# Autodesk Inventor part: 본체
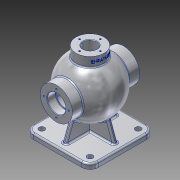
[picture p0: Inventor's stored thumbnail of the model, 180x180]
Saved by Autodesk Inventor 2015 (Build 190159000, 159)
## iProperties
Created: 2025-08
Part Number: 본체
Material: 알루미늄 6061
Document SubType Name: Modeling
Designer: USER
Density: 2.7 g/cm^3
Appearance: 알루미늄 - 평지
Mass: 1526.21 g
Surface Area: 1175.8 cm^2
Volume: 565.262 cm^3
Author: USER
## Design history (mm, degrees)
sketch "스케치1"
  geometry: L1 (-62.5, 62.5)-(62.5, 62.5); L2 (62.5, 62.5)-(62.5, -62.5); L3 (62.5, -62.5)-(-62.5, -62.5); L4 (-62.5, -62.5)-(-62.5, 62.5); L5 (-62.5, 62.5)-(62.5, -62.5); L6 (62.5, 62.5)-(-62.5, -62.5); 1 further point
  constraints: 12 end point, 2 midpoint, 2 parallel, 1 horizontal, 1 perpendicular
  dimensions: "d0" = 125 distance of L2.end L3.end; "d1" = 125 distance of L1.end L2.end
extrude "돌출1" new body sketch "스케치1" distance "d2" = 10; taper "d3" = 0 deg
sketch "스케치2"
  geometry: L1 (0, 139)-(0, 130); L2 (0, 130)-(0, 31); L3 (62.5, 10)-(62.5, 0) reference; L4 (62.5, 0)-(-62.5, 0) reference; L5 (-62.5, 0)-(-62.5, 10) reference; L6 (-62.5, 10)-(62.5, 10) reference; A1 r 54 centre (0, 85) between (0, 139) and (0, 31); 2 further points
  constraints: 4 end point, 2 point on circle, 2 point on line, 1 centre point, 1 midpoint, 1 vertical, 1 vertical alignment
  dimensions: "d4" = 108 diameter of A1; "d5" = 85 distance from line of A1.centre L4
revolve "회전1" sketch "스케치2" stored, may be unused: angle "d6" = 90 deg
sketch "스케치3"
  geometry: L1 (62.5, 62.5)-(62.5, -62.5) reference; L2 (62.5, -62.5)-(-62.5, -62.5) reference; L3 (-62.5, -62.5)-(-62.5, 62.5) reference; L4 (-62.5, 62.5)-(62.5, 62.5) reference; L5 (-4, 50.5)-(4, 50.5); L6 (4, 50.5)-(4, -50.5); L7 (4, -50.5)-(-4, -50.5); L8 (-4, -50.5)-(-4, 50.5); L9 (-50.5, 4)-(50.5, 4); L10 (50.5, 4)-(50.5, -4); L11 (50.5, -4)-(-50.5, -4); L12 (-50.5, -4)-(-50.5, 4); 1 further point
  constraints: 16 end point, 4 parallel, 2 horizontal, 2 perpendicular
  dimensions: "d7" = 8 distance of L5.end L5.start; "d8" = 12 distance between parallel lines of L5 L4; "d9" = 12 distance between parallel lines of L2 L7; "d10" = 4 distance from line of L8 point (0, 0); "d11" = 8 distance of L11.end L9.start; "d12" = 12 distance between parallel lines of L12 L3; "d13" = 12 distance between parallel lines of L1 L10; "d14" = 4 distance from line of point (0, 0) L9
extrude "돌출2" join sketch "스케치3" stored distance "d15" = 10; taper "d16" = 0 deg
feature "면 기울기1" dims angle "d17" = 20 deg
feature "면 기울기2" dims angle "d18" = 20 deg
feature "면 기울기3" dims angle "d19" = 20 deg
feature "면 기울기4" dims angle "d20" = 20 deg
node "작업 평면1"
sketch "스케치4"
  geometry: C1 r 27 at (0, 0); 1 further point
  constraints: 1 centre point, 1 coincident
  dimensions: "d22" = 54 diameter of C1
extrude "돌출3" join sketch "스케치4" stored distance "d23" = 10; taper "d24" = 0 deg
node "작업 평면2"
sketch "스케치5"
  geometry: C1 r 31 at (0, 85); 1 further point
  constraints: 1 centre point, 1 vertical alignment
  dimensions: "d26" = 62 diameter of C1; "d27" = 85 distance of C1.centre point (0, 0)
extrude "돌출4" join sketch "스케치5" distance "d28" = 130; taper "d29" = 0 deg
sketch "스케치6"
  geometry: L1 (62.5, 0)-(-62.5, 0) reference; L2 (-62.5, 0)-(-62.5, 10) reference; L3 (-62.5, 10)-(-50.5, 10) reference; L4 (-50.5, 10)-(-37.385, 46.034) reference; L5 (-27, 131.765)-(-27, 150) reference; L6 (-27, 150)-(27, 150) reference; L7 (27, 150)-(27, 131.765) reference; L8 (37.385, 46.034)-(50.5, 10) reference; L9 (50.5, 10)-(62.5, 10) reference; L10 (62.5, 10)-(62.5, 0) reference; L11 (0, 129)-(0, 41); A1 r 54 centre (0, 85) between (-27, 131.765) and (-37.385, 46.034) reference; A2 r 54 centre (0, 85) between (37.385, 46.034) and (27, 131.765) reference; A3 r 44 centre (0, 85) between (0, 129) and (0, 41); 1 further point
  constraints: 2 end point, 2 point on circle, 1 centre point, 1 coincident, 1 vertical
  dimensions: "d30" = 88 diameter of A3
revolve "회전2" sketch "스케치6" stored, may be unused: angle "d31" = 360 deg
sketch "스케치7"
  geometry: 1 further point
fillet "모깎기1" dims "d33" = 16
fillet "모깎기2" dims "d34" = 16
sketch "스케치9"
  geometry: 1 further point
hole "구멍1" diameter "d37" = 11; stored, may be unused: countersink angle "d41" = 90 deg, drill point angle "d43" = 0 deg; dims "d38" = 6, "d39" = 4, "d40" = 2, "d42" = 8, "d116" = 10, "d117" = 10
hole "구멍2" diameter "d51" = 30; stored, may be unused: countersink angle "d55" = 90 deg, drill point angle "d57" = 0 deg; dims "d49" = 10, "d50" = 10, "d52" = 6, "d53" = 4, "d54" = 2, "d56" = 8
sketch "스케치11"
  geometry: L1 (0, 0)-(0, 24); 1 further point
  constraints: 2 end point, 1 vertical
  dimensions: "d58" = 24 distance of L1.start L1.end
hole "구멍3" sketch "스케치11" at (0, 24) diameter "d59" = 3.242; stored, may be unused: countersink angle "d63" = 90 deg, drill point angle "d65" = 118 deg; dims "d60" = 12, "d61" = 4, "d62" = 2, "d64" = 15
hole "구멍4" diameter "d68" = 26; stored, may be unused: countersink angle "d72" = 90 deg, drill point angle "d74" = 0 deg; dims "d66" = 10, "d67" = 10, "d69" = 8, "d70" = 4, "d71" = 2, "d73" = 100
sketch "스케치12"
  geometry: 1 further point
sketch "스케치14"
  geometry: C1 r 17.5 at (0, 0); 1 further point
  constraints: 1 centre point
  dimensions: "d78" = 35 diameter of C1
extrude "돌출5" cut sketch "스케치14" distance "d79" = 16; taper "d80" = 0 deg
sketch "스케치15"
  geometry: C1 r 17.5 at (0, 0); 1 further point
  constraints: 1 centre point
  dimensions: "d81" = 35 diameter of C1
extrude "돌출6" cut sketch "스케치15" distance "d82" = 16; taper "d83" = 0 deg
sketch "스케치16"
  geometry: L1 (0, 0)-(0, 20)
  constraints: 2 end point, 1 vertical
  dimensions: "d84" = 20 distance of L1.start L1.end
hole "구멍5" sketch "스케치16" at (0, 20) diameter "d85" = 3.242; stored, may be unused: countersink angle "d89" = 90 deg, drill point angle "d91" = 118 deg; dims "d86" = 9, "d87" = 4, "d88" = 2, "d90" = 11
fillet "모깎기3" dims "d95" = 3
fillet "모깎기4" dims "d96" = 3
fillet "모깎기5" dims "d97" = 3
fillet "모깎기6" dims "d98" = 3
fillet "모깎기7" dims "d99" = 3
sketch "스케치17"
  geometry: L1 (-13, 150)-(13, 150) reference; 2 further points
  constraints: 1 vertical alignment, 1 other
  dimensions: "d102" = 9 distance from line of point (0, 141) L1
feature "엠보싱2" sketch "스케치17" dims "d103" = 0.5, "d104" = 0
sketch "스케치18"
  geometry: 1 further point
sketch "스케치19"
  geometry: 1 further point
fillet "모깎기8" dims "d114" = 0.6
chamfer "모따기4" distance "d115" = 1; stored, may be unused: second distance "d118" = 2, angle "d119" = 45 deg
node "솔리드1"
pattern_linear "직사각형 패턴1" dims "d48" = 93
mirror "대칭1"
pattern_circular "원형 패턴1" dims angle "d76" = 360 deg
mirror "대칭2"
pattern_circular "원형 패턴2" dims angle "d93" = 360 deg
node "절단 모서리 투영1"
node "절단 모서리 투영2"
node "절단 모서리 투영3"
other parameters: "d25" = -65
